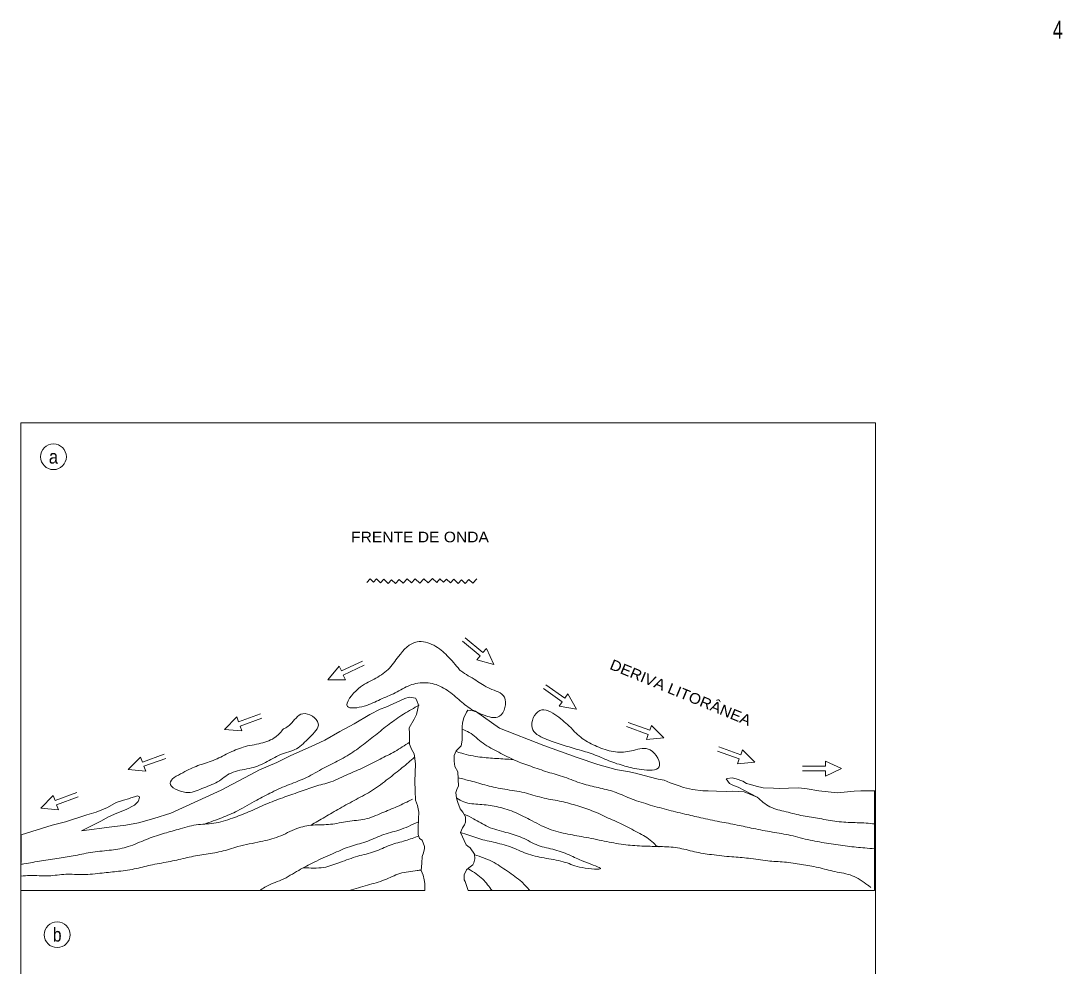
# Model space of a CAD drawing. Extents: x 32 to 150, y 1 to 212.
# Drawn here: x 32.2 to 150, y 104.8 to 211.7 of the extents above; entities that cross this region are included whole.
import ezdxf
from ezdxf.enums import TextEntityAlignment as Align

# ---------------------------------------------------------------- set-up
doc = ezdxf.new("R2010")
doc.units = 0
doc.header["$LTSCALE"] = 0.48
doc.layers.add('1', color=7, linetype='Continuous', lineweight=13)
doc.layers.add('44', color=7, linetype='Continuous', lineweight=13)

msp = doc.modelspace()

# ---------------------------------------------------------------- linework, layer by layer
at = {"layer": '1'}
for p, q in [((81.8408, 138.2554), (81.8197, 138.3017)), ((62.1686, 131.7258), (61.9096, 131.6116)), ((94.6641, 131.4716), (94.4048, 131.7534)), ((128.7773, 113.3174), (128.7773, 124.563)), ((32.1837, 113.3174), (77.898, 113.3174)), ((82.7982, 113.3174), (128.772, 113.3174))]:
    msp.add_line(p, q, dxfattribs=at)
msp.add_lwpolyline([(32.1837, 55.2831), (128.8829, 55.2831), (128.8829, 166.2104), (32.1837, 166.2104)], close=True, dxfattribs=at)
for points in [[(71.3415, 148.1791), (71.7125, 148.5722), (72.0997, 148.2072), (72.435, 148.5638), (72.8901, 148.1368), (73.2605, 148.531), (73.751, 148.0676), (74.1335, 148.4747), (74.5624, 148.069), (74.9792, 148.5105), (75.4346, 148.0851), (75.895, 148.5737), (76.3744, 148.1234), (76.8118, 148.5892), (77.3256, 148.1047), (77.7875, 148.5956), (78.2773, 148.1333), (78.7505, 148.6356), (79.2404, 148.1733)], [(79.2404, 148.1733), (79.6111, 148.5647), (79.9992, 148.2005), (80.3344, 148.5571), (80.7885, 148.1295), (81.1601, 148.5241), (81.6494, 148.0628), (82.0324, 148.4691), (82.4621, 148.0622), (82.8792, 148.5052), (83.3331, 148.0776), (83.7949, 148.5686)], [(82.144, 141.5353), (84.15, 139.8521), (83.7702, 139.3996), (85.6877, 138.8932)], [(82.4704, 141.9241), (84.4762, 140.241), (84.8559, 140.6936), (85.6877, 138.8932)], [(70.8291, 139.2624), (68.4559, 138.1557), (68.2063, 138.6911), (66.9369, 137.1674)], [(71.0436, 138.8023), (68.6705, 137.6957), (68.9202, 137.1603), (66.9369, 137.1674)], [(91.3056, 136.1657), (93.4505, 134.6639), (93.1116, 134.18), (95.066, 133.8426)], [(91.5967, 136.5815), (93.7416, 135.0797), (94.0805, 135.5636), (95.066, 133.8426)], [(77.898, 113.3174), (77.8806, 114.1181), (77.8227, 114.5316), (77.7009, 115.0613), (77.4909, 115.5934), (77.5516, 116.4156), (77.611, 117.1692), (77.7296, 117.5778), (77.8496, 118.055), (77.8543, 118.2837), (77.5817, 119.0007), (77.2769, 119.215), (77.1533, 119.6533), (77.146, 120.3858), (77.1893, 121.4372), (77.204, 122.1691), (77.0653, 122.951), (76.8566, 123.5517), (76.8116, 124.6056), (76.7672, 125.6824), (76.8501, 127.6024), (76.7527, 128.2458), (76.6755, 128.7972), (76.3988, 129.3083), (76.1671, 129.8638), (76.1695, 131.0767), (76.1383, 131.7183), (76.1383, 131.7183), (76.6877, 132.6872), (76.9416, 133.2294), (77.0836, 133.706), (77.1839, 134.2982), (76.996, 134.8298), (76.824, 135.0633), (76.1202, 135.1972), (75.631, 135.0276), (74.718, 134.6408), (73.4703, 134.0802), (72.8248, 133.8233), (71.6865, 133.2139), (69.8991, 132.1648), (68.2702, 131.3172), (66.5724, 130.3341), (65.0341, 129.5984), (62.7175, 128.5867), (61.1342, 127.8064), (59.1964, 126.9674), (57.5671, 126.0969), (56.072, 125.3143), (54.8671, 124.6838), (49.1401, 122.0726), (47.2291, 121.4615), (45.4968, 120.9601), (44.079, 120.7245), (42.4636, 120.5401), (39.0317, 120.0626), (40.3475, 120.7128), (41.2178, 121.1695), (42.0886, 121.6489), (43.0466, 122.0802), (44.1145, 122.4856), (45.0299, 122.9867), (45.4575, 123.3868), (45.5034, 123.4771), (45.5991, 123.8406), (45.6005, 123.9093), (45.3821, 124.0297), (45.0268, 123.925), (44.6489, 123.7981), (44.3818, 123.6911), (43.8048, 123.5468), (42.9823, 123.272), (41.9999, 122.7269), (40.7085, 122.1904), (39.6649, 121.8988), (37.2201, 121.0965), (35.7328, 120.7027), (32.2224, 119.6094), (32.1837, 113.3174)], [(59.2851, 133.2943), (56.8245, 132.3987), (56.6225, 132.9538), (55.2251, 131.5465)], [(128.8002, 124.608), (127.2174, 124.6131), (126.4653, 124.5422), (124.607, 124.3646), (122.4924, 124.606), (121.1721, 124.8254), (120.1809, 124.9442), (119.0316, 124.8843), (118.0157, 124.8666), (117.3537, 124.8848), (116.1626, 124.9405), (115.3935, 125.1218), (115.0202, 125.2237), (114.2957, 125.4267), (113.8594, 125.6905), (113.1143, 125.9627), (112.6747, 126.0664), (112.0992, 125.9907), (112.01, 125.9473), (112.3745, 125.411), (112.7465, 125.2406), (113.3601, 125.0177), (115.5009, 123.8832), (114.6689, 124.2264), (114.012, 124.4962), (112.7326, 124.5544), (111.9814, 124.5294), (110.9001, 124.5591), (109.9734, 124.5846), (109.3555, 124.6016), (108.1662, 124.7489), (107.1553, 124.9826), (106.6731, 125.1561), (105.6646, 125.5042), (104.9865, 125.8204), (104.3042, 125.9308), (103.2717, 126.1881), (101.7345, 126.5966), (100.8771, 126.7804), (100.1287, 126.8925), (99.4911, 127.0245), (97.4707, 127.5608), (95.1244, 128.3576), (91.3543, 129.7201), (86.338, 131.689), (83.6167, 133.5947), (82.78, 133.7093), (82.5988, 133.4854), (82.299, 132.8529), (82.1551, 132.2848), (82.1243, 131.8509), (82.1118, 131.2334), (82.1375, 130.3173), (81.9922, 129.6805), (81.7214, 129.3904), (81.429, 129.124), (81.2197, 128.6034), (81.2289, 127.9623), (81.2831, 127.3659), (81.6242, 126.7615), (81.7012, 125.1117), (81.5638, 124.8637), (81.4001, 124.4106), (81.4975, 123.7672), (81.6202, 123.2832), (81.8928, 122.5663), (82.1938, 122.1689), (82.4926, 121.6573), (82.4806, 121.0627), (82.3859, 120.7449), (82.1583, 120.4078), (81.9265, 119.865), (82.5834, 118.4968), (82.7792, 118.354), (83.0182, 118.1644), (83.5331, 117.4179), (83.567, 116.9136), (83.4475, 116.4592), (83.31, 116.2112), (82.8843, 115.9026), (82.6144, 115.6582), (82.3601, 115.0931), (82.3491, 114.5442), (82.4773, 114.3348), (82.7982, 113.3174)], [(59.4587, 132.8173), (56.9981, 131.9217), (57.2002, 131.3666), (55.2251, 131.5465)], [(100.8883, 132.3447), (103.3488, 131.4491), (103.5509, 132.0042), (104.9482, 130.5969)], [(100.7147, 131.8677), (103.1752, 130.9721), (102.9732, 130.417), (104.9482, 130.5969)], [(48.4048, 128.7443), (45.9442, 127.8488), (45.7421, 128.4039), (44.3448, 126.9965)], [(111.0016, 129.0981), (113.4622, 128.2025), (113.2601, 127.6474), (115.2352, 127.8273)], [(111.1752, 129.5751), (113.6358, 128.6795), (113.8378, 129.2347), (115.2352, 127.8273)], [(48.5784, 128.2673), (46.1178, 127.3718), (46.3198, 126.8166), (44.3448, 126.9965)], [(120.6293, 127.3697), (123.2478, 127.3697), (123.2478, 127.9604), (125.0422, 127.1159)], [(120.6293, 126.8621), (123.2478, 126.8621), (123.2478, 126.2713), (125.0422, 127.1159)], [(38.5135, 124.3921), (36.0529, 123.4965), (35.8508, 124.0516), (34.4535, 122.6443)], [(38.6871, 123.9151), (36.2265, 123.0195), (36.4285, 122.4644), (34.4535, 122.6443)]]:
    msp.add_lwpolyline(points, dxfattribs=at)
for centre in [(35.8754, 162.3911), (36.2965, 108.3211)]:
    msp.add_circle(centre, 1.458, dxfattribs=at)
for points in [[(81.8197, 138.3017), (80.4384, 139.8729), (78.9168, 141.059), (77.026, 141.4544), (74.9172, 139.7962), (73.7393, 138.3183), (72.1499, 137.2408), (70.3841, 136.1681), (69.1289, 134.1431), (71.0506, 134.1817), (72.8541, 134.9329), (74.5472, 135.6872), (76.2202, 136.5337), (78.0587, 136.8262), (79.8152, 136.343), (81.3823, 135.2243), (82.7939, 134.0642), (84.4985, 133.1934), (86.3277, 133.0285), (86.9012, 135.1867), (85.2431, 136.1707), (83.6722, 137.1064), (81.9714, 138.1601), (81.8408, 138.2554)], [(61.9096, 131.6116), (61.0228, 130.7049), (59.3522, 129.9728), (57.3565, 129.5472), (55.6422, 128.8393), (53.948, 128.0393), (52.214, 127.4463), (50.4978, 126.6468), (49.0832, 125.4729), (50.8502, 124.4173), (52.6693, 124.8478), (54.4512, 125.6225), (55.9726, 126.6104), (58.0363, 127.1257), (59.86, 127.7848), (61.5564, 128.6992), (63.3802, 129.3584), (64.8413, 130.6455), (65.8445, 132.2197), (64.0783, 133.321), (62.6628, 132.1014), (62.1686, 131.7258)], [(52.9649, 120.8378), (54.9432, 121.5585), (56.7031, 122.3338), (58.869, 123.5328), (60.587, 124.4237), (62.5478, 125.308), (64.5066, 126.1008), (66.4491, 127.1685), (68.2112, 128.0583), (69.9546, 129.1087), (71.5241, 130.3012), (73.0721, 131.5172), (74.6417, 132.7097), (76.3859, 133.8058), (77.2567, 134.2854)], [(94.4048, 131.7534), (92.8419, 133.0779), (90.9112, 133.6804), (90.0324, 131.7136), (91.4653, 130.5071), (93.3285, 129.8378), (95.1498, 129.2842), (96.9491, 128.7312), (98.7227, 127.9959), (100.5431, 127.3965), (102.4119, 127.0018), (104.4052, 127.313), (103.4059, 129.217), (101.5064, 129.1778), (99.6919, 128.9761), (97.8245, 129.4394), (96.0969, 130.2651), (94.6857, 131.4481), (94.6641, 131.4716)], [(82.1187, 131.5721), (82.9128, 131.2004), (84.478, 129.9901), (86.2677, 128.9568), (88.1257, 128.036), (89.8786, 127.3699), (91.8084, 126.7218), (93.6955, 126.1434), (95.6902, 125.4249), (97.5133, 124.9627), (99.3361, 124.4777), (101.088, 123.7658), (103.1493, 123.0682), (105.2351, 122.4845), (107.3, 121.9699), (109.1242, 121.5535), (111.2568, 121.1058), (113.2362, 120.7308), (115.0608, 120.3373), (117.2164, 119.9347), (119.2842, 119.5573), (121.4812, 119.0162), (123.6151, 118.6371), (125.7284, 118.3271), (127.6895, 118.1358), (128.7773, 118.0368)], [(76.1788, 130.1043), (74.5016, 129.052), (72.8282, 128.1828), (71.0435, 127.2709), (69.239, 126.4738), (67.2567, 125.6131), (65.4578, 125.0905), (63.6791, 124.4759), (61.8112, 123.8179), (59.8973, 123.0697), (57.937, 122.2084), (56.1344, 121.5028), (54.0031, 120.9207), (52.0346, 120.7461), (49.9708, 120.2309), (48.2166, 119.73), (46.3712, 119.0943), (44.3457, 118.2805), (42.4391, 117.8982), (40.3147, 117.6592), (38.3421, 117.2788), (36.5257, 116.9856), (34.5323, 116.6743), (32.5386, 116.3402), (32.202, 116.2878)], [(87.8815, 128.1426), (86.0327, 128.2539), (84.1373, 128.4205), (82.0704, 128.8436), (81.4059, 129.0664)], [(64.9893, 120.6911), (66.5801, 121.627), (68.2779, 122.61), (70.1311, 123.6345), (71.9622, 124.6596), (73.7548, 125.9604), (75.3479, 127.2209), (76.7324, 128.3903)], [(81.6571, 126.0558), (83.0452, 125.7274), (84.9332, 125.1948), (86.9339, 124.7735), (89.1341, 124.3926), (91.132, 123.8341), (93.133, 123.4357), (94.9563, 122.9735), (96.7983, 122.3507), (98.6582, 121.5214), (100.4084, 120.718), (102.2213, 119.7527), (103.7678, 118.7032), (104.3773, 118.2746), (104.3994, 118.2739)], [(81.499, 123.761), (82.3127, 123.3447), (84.1176, 123.0662), (85.989, 122.8087), (87.9202, 122.2292), (89.7572, 121.3547), (91.9435, 120.2876), (94.0734, 119.7026), (96.1411, 119.3252), (98.4939, 118.8485), (100.6283, 118.4922), (102.7008, 118.3436), (104.5323, 118.2931), (106.4944, 118.1476), (108.4062, 117.7058), (110.3426, 117.3779), (112.6338, 117.1317), (114.5292, 116.965), (116.687, 116.6768), (118.5829, 116.533), (120.5206, 116.2737), (122.3902, 115.9247), (124.3017, 115.4602), (126.2573, 114.9943), (128.0023, 113.9394), (128.3719, 113.6546)], [(115.5009, 123.8832), (116.9432, 122.8027), (118.764, 122.2262), (120.6976, 121.7611), (122.5682, 121.4578), (124.5265, 121.1293), (126.5773, 121.0041), (128.5619, 120.8808), (128.7773, 120.8562)], [(76.49, 123.6424), (74.7733, 122.8201), (73.0364, 122.0899), (71.1234, 121.3874), (69.1757, 121.1436), (67.2259, 120.8082), (65.2592, 120.7251), (63.3965, 120.3187), (61.3469, 119.414), (59.3044, 118.8524), (56.7539, 118.2819), (54.8442, 117.7396), (52.8945, 117.4042), (51.0105, 117.0442), (49.1252, 116.6156), (47.0862, 116.237), (45.2672, 115.8065), (43.2517, 115.4959), (41.393, 115.2954), (39.2259, 115.1262), (37.2836, 115.1568), (35.3152, 114.9822), (33.1963, 115.0177), (32.1938, 114.9599)], [(82.3096, 121.9708), (83.4003, 121.4382), (85.0598, 120.5229), (87.0783, 119.8953), (88.9208, 119.2952), (90.7137, 118.4221), (92.6026, 117.9352), (94.4432, 117.2438), (96.1285, 116.5108), (97.7922, 115.8014), (95.6968, 115.9048), (93.7881, 116.5066), (91.6554, 116.9544), (89.6337, 117.422), (87.8381, 118.158), (85.8848, 118.7381), (83.9953, 119.2021), (82.1754, 119.8244), (81.9407, 119.8983)], [(77.1223, 121.0619), (74.9625, 120.1603), (73.0297, 119.5728), (71.2042, 118.8222), (69.3607, 118.278), (67.4454, 117.4611), (65.3734, 116.5341), (63.6324, 115.5981), (61.69, 114.5303), (59.7743, 113.6906), (59.203, 113.3174)], [(64.1837, 115.8998), (66.4431, 115.9326), (68.2871, 116.4997), (70.3104, 117.1991), (72.1975, 117.7192), (73.9785, 118.4482), (75.7113, 118.9726), (77.1984, 119.4932)], [(83.5368, 117.3628), (85.5104, 116.5973), (87.2545, 115.4966), (88.8638, 114.2852), (89.7922, 113.3174)], [(77.4942, 115.6389), (77.0336, 115.5722), (75.0618, 115.2375), (73.3475, 114.5296), (71.3923, 113.9197), (69.3615, 113.3174)], [(82.7581, 115.7884), (82.8656, 115.732), (84.4542, 114.5898), (85.4967, 113.3174)]]:
    msp.add_spline(points, degree=3, dxfattribs=at)
at = {"layer": '44'}
msp.add_lwpolyline([(32.1837, 55.2831), (128.8829, 55.2831), (128.8829, 166.2104), (32.1837, 166.2104)], close=True, dxfattribs=at)

# ---------------------------------------------------------------- texts
at = {"layer": '1', "width": 0.75}
msp.add_text('4', height=2, dxfattribs=at).set_placement((148.9528, 209.7067))
at = {"layer": '1'}
for s, height, width, p in [('a', 1.555, 0.9, (35.8745, 161.6139)), ('FRENTE DE ONDA', 1.2, 1.1, (77.346, 152.7131)), ('b', 1.555, 0.85, (36.2968, 107.5435))]:
    msp.add_text(s, height=height, dxfattribs=dict(at, width=width)).set_placement(p, align=Align.CENTER)
at = {"layer": '1', "width": 1.1}
msp.add_text('DERIVA LITORÂNEA', height=1.2, rotation=337.636, dxfattribs=at).set_placement((106.6082, 135.1658), align=Align.CENTER)

doc.saveas('drawing.dxf')
